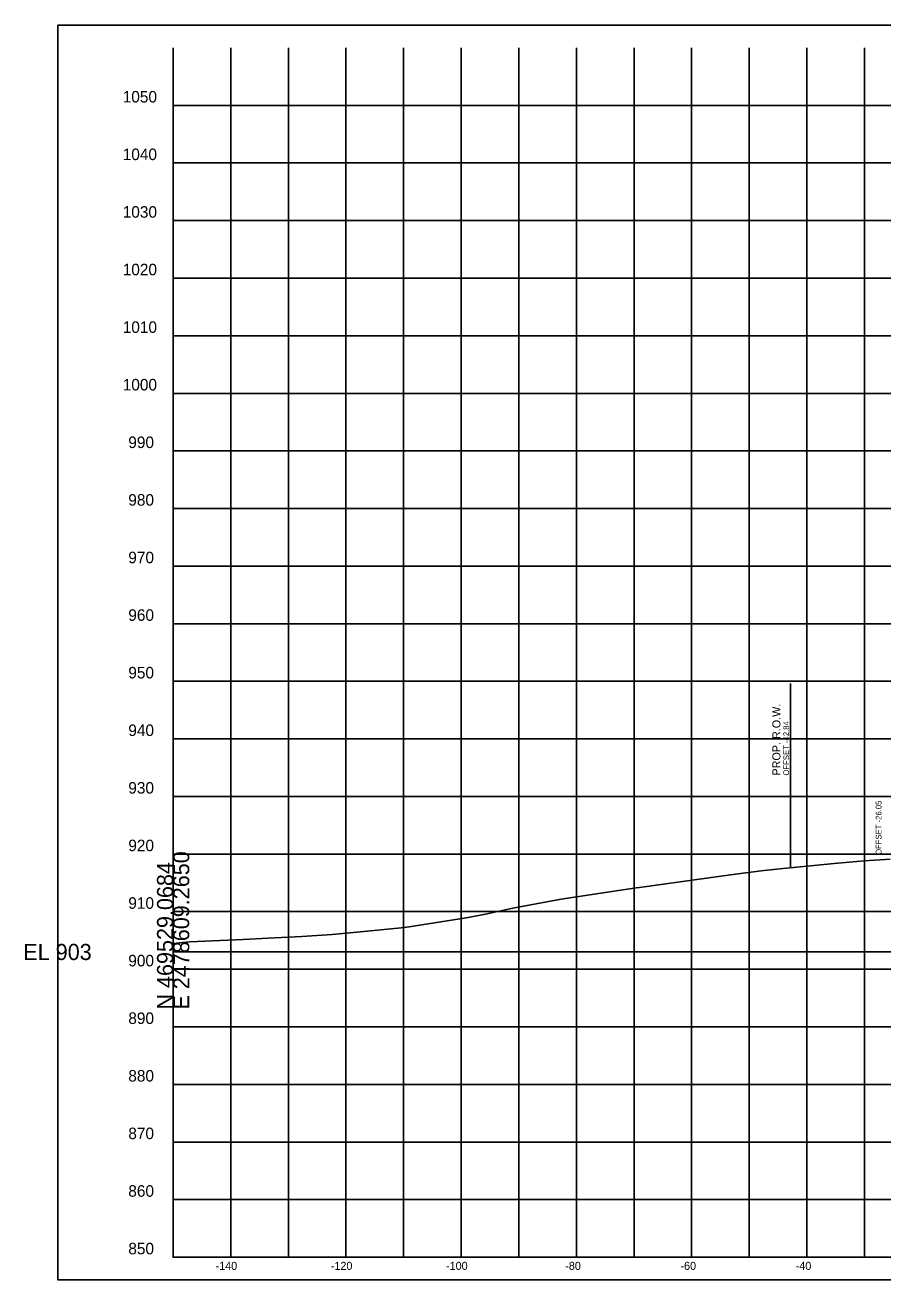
# Model space of a CAD drawing. Extents: x -26 to 2478923, y -10 to 469990.
# Drawn here: x -25.7 to 123.2, y 6943.1 to 7160.9 of the extents above; entities that cross this region are included whole.
import ezdxf

# ---------------------------------------------------------------- set-up
doc = ezdxf.new("R2010")
doc.units = 0
for name, color, linetype in [('DESIGN - ROW - Right-of-Way and Easement Labels', 7, 'Continuous'), ('DESIGN - ROW - Right-of-Way Linework', 7, 'Continuous'), ('DESIGN - SHEET - Corner Text', 7, 'Continuous'), ('DESIGN - SHEET - Light Grid', 7, 'Continuous'), ('DESIGN - SHEET - Linework', 7, 'Continuous'), ('DESIGN - SHEET - Plot Shape', 7, 'Continuous'), ('DESIGN - TYPICAL - Slope Tie Text', 7, 'Continuous'), ('SURVEY - GROUND - Top of Ground', 7, 'Continuous')]:
    doc.layers.add(name, color=color, linetype=linetype)

msp = doc.modelspace()

# ---------------------------------------------------------------- linework, layer by layer
at = {"layer": 'DESIGN - ROW - Right-of-Way Linework'}
msp.add_line((107.16, 7014.63), (107.16, 7046.63), dxfattribs=at)
at = {"layer": 'DESIGN - SHEET - Light Grid'}
msp.add_line((0, 7000), (150, 7000), dxfattribs=at)
at = {"layer": 'DESIGN - SHEET - Linework'}
for p, q in [((10, 6947), (10, 7157)), ((10, 6947), (10, 7157)), ((10, 6947), (10, 7157)), ((10, 6947), (10, 7157)), ((20, 6947), (20, 7157)), ((20, 6947), (20, 7157)), ((20, 6947), (20, 7157)), ((20, 6947), (20, 7157)), ((30, 6947), (30, 7157)), ((30, 6947), (30, 7157)), ((30, 6947), (30, 7157)), ((30, 6947), (30, 7157)), ((40, 6947), (40, 7157)), ((40, 6947), (40, 7157)), ((40, 6947), (40, 7157)), ((40, 6947), (40, 7157)), ((50, 6947), (50, 7157)), ((50, 6947), (50, 7157)), ((50, 6947), (50, 7157)), ((50, 6947), (50, 7157)), ((60, 6947), (60, 7157)), ((60, 6947), (60, 7157)), ((60, 6947), (60, 7157)), ((60, 6947), (60, 7157)), ((70, 6947), (70, 7157)), ((70, 6947), (70, 7157)), ((70, 6947), (70, 7157)), ((70, 6947), (70, 7157)), ((80, 6947), (80, 7157)), ((80, 6947), (80, 7157)), ((80, 6947), (80, 7157)), ((80, 6947), (80, 7157)), ((90, 6947), (90, 7157)), ((90, 6947), (90, 7157)), ((90, 6947), (90, 7157)), ((90, 6947), (90, 7157)), ((100, 6947), (100, 7157)), ((100, 6947), (100, 7157)), ((100, 6947), (100, 7157)), ((100, 6947), (100, 7157)), ((110, 6947), (110, 7157)), ((110, 6947), (110, 7157)), ((110, 6947), (110, 7157)), ((110, 6947), (110, 7157)), ((120, 6947), (120, 7157)), ((120, 6947), (120, 7157)), ((120, 6947), (120, 7157)), ((120, 6947), (120, 7157)), ((0, 7147), (300, 7147)), ((0, 7147), (300, 7147)), ((0, 7147), (300, 7147)), ((0, 7147), (300, 7147)), ((0, 7137), (300, 7137)), ((0, 7137), (300, 7137)), ((0, 7137), (300, 7137)), ((0, 7137), (300, 7137)), ((0, 7127), (300, 7127)), ((0, 7127), (300, 7127)), ((0, 7127), (300, 7127)), ((0, 7127), (300, 7127)), ((0, 7117), (300, 7117)), ((0, 7117), (300, 7117)), ((0, 7117), (300, 7117)), ((0, 7117), (300, 7117)), ((0, 7107), (300, 7107)), ((0, 7107), (300, 7107)), ((0, 7107), (300, 7107)), ((0, 7107), (300, 7107)), ((0, 7097), (300, 7097)), ((0, 7097), (300, 7097)), ((0, 7097), (300, 7097)), ((0, 7097), (300, 7097)), ((0, 7087), (300, 7087)), ((0, 7087), (300, 7087)), ((0, 7087), (300, 7087)), ((0, 7087), (300, 7087)), ((0, 7077), (300, 7077)), ((0, 7077), (300, 7077)), ((0, 7077), (300, 7077)), ((0, 7077), (300, 7077)), ((0, 7067), (300, 7067)), ((0, 7067), (300, 7067)), ((0, 7067), (300, 7067)), ((0, 7067), (300, 7067)), ((0, 7057), (300, 7057)), ((0, 7057), (300, 7057)), ((0, 7057), (300, 7057)), ((0, 7057), (300, 7057)), ((0, 7047), (300, 7047)), ((0, 7047), (300, 7047)), ((0, 7047), (300, 7047)), ((0, 7047), (300, 7047)), ((0, 7037), (300, 7037)), ((0, 7037), (300, 7037)), ((0, 7037), (300, 7037)), ((0, 7037), (300, 7037)), ((0, 7027), (300, 7027)), ((0, 7027), (300, 7027)), ((0, 7027), (300, 7027)), ((0, 7027), (300, 7027)), ((0, 7017), (300, 7017)), ((0, 7017), (300, 7017)), ((0, 7017), (300, 7017)), ((0, 7017), (300, 7017)), ((0, 7007), (300, 7007)), ((0, 7007), (300, 7007)), ((0, 7007), (300, 7007)), ((0, 7007), (300, 7007)), ((0, 6997), (300, 6997)), ((0, 6997), (300, 6997)), ((0, 6997), (300, 6997)), ((0, 6997), (300, 6997)), ((0, 6987), (300, 6987)), ((0, 6987), (300, 6987)), ((0, 6987), (300, 6987)), ((0, 6987), (300, 6987)), ((0, 6977), (300, 6977)), ((0, 6977), (300, 6977)), ((0, 6977), (300, 6977)), ((0, 6977), (300, 6977)), ((0, 6967), (300, 6967)), ((0, 6967), (300, 6967)), ((0, 6967), (300, 6967)), ((0, 6967), (300, 6967)), ((0, 6957), (300, 6957)), ((0, 6957), (300, 6957)), ((0, 6957), (300, 6957)), ((0, 6957), (300, 6957))]:
    msp.add_line(p, q, dxfattribs=at)
msp.add_lwpolyline([(0, 7157), (0, 6947), (300, 6947), (300, 7157)], dxfattribs=at)
msp.add_lwpolyline([(0, 7157), (0, 6947), (300, 6947), (300, 7157)], dxfattribs=at)
msp.add_lwpolyline([(0, 7157), (0, 6947), (300, 6947), (300, 7157)], dxfattribs=at)
msp.add_lwpolyline([(0, 7157), (0, 6947), (300, 6947), (300, 7157)], dxfattribs=at)
at = {"layer": 'DESIGN - SHEET - Plot Shape'}
msp.add_lwpolyline([(-20, 7160.94), (320, 7160.94), (320, 6943.06), (-20, 6943.06)], close=True, dxfattribs=at)
msp.add_lwpolyline([(-20, 7160.94), (320, 7160.94), (320, 6943.06), (-20, 6943.06)], close=True, dxfattribs=at)
msp.add_lwpolyline([(-20, 7160.94), (320, 7160.94), (320, 6943.06), (-20, 6943.06)], close=True, dxfattribs=at)
msp.add_lwpolyline([(-20, 7160.94), (320, 7160.94), (320, 6943.06), (-20, 6943.06)], close=True, dxfattribs=at)
at = {"layer": 'SURVEY - GROUND - Top of Ground'}
msp.add_lwpolyline([(0, 7001.49), (2.84, 7001.75), (12.16, 7002.18), (16.51, 7002.4), (22.32, 7002.66), (27.62, 7003.04), (33.08, 7003.58), (40.14, 7004.26), (40.48, 7004.29), (40.96, 7004.36), (50.85, 7005.92), (54.22, 7006.57), (58.97, 7007.63), (67.37, 7009.19), (80.36, 7011.14), (80.93, 7011.22), (92.57, 7012.8), (96.75, 7013.4), (102.07, 7014.08), (105.89, 7014.51), (114.71, 7015.38), (117.35, 7015.6), (119.98, 7015.82), (124.47, 7016.14)], dxfattribs=at)

# ---------------------------------------------------------------- texts
at = {"layer": 'DESIGN - ROW - Right-of-Way and Easement Labels'}
for s, height, p in [('PROP. R.O.W.', 1.4, (105.41, 7030.63)), ('OFFSET -42.84', 1, (106.91, 7030.63))]:
    msp.add_text(s, height=height, rotation=90, dxfattribs=at).set_placement(p)
at = {"layer": 'DESIGN - SHEET - Corner Text'}
for s, height, p in [('1050', 2, (-8.75, 7147.5)), ('1050', 2, (-8.75, 7147.5)), ('1050', 2, (-8.75, 7147.5)), ('1050', 2, (-8.75, 7147.5)), ('1040', 2, (-8.75, 7137.5)), ('1040', 2, (-8.75, 7137.5)), ('1040', 2, (-8.75, 7137.5)), ('1040', 2, (-8.75, 7137.5)), ('1030', 2, (-8.75, 7127.5)), ('1030', 2, (-8.75, 7127.5)), ('1030', 2, (-8.75, 7127.5)), ('1030', 2, (-8.75, 7127.5)), ('1020', 2, (-8.75, 7117.5)), ('1020', 2, (-8.75, 7117.5)), ('1020', 2, (-8.75, 7117.5)), ('1020', 2, (-8.75, 7117.5)), ('1010', 2, (-8.75, 7107.5)), ('1010', 2, (-8.75, 7107.5)), ('1010', 2, (-8.75, 7107.5)), ('1010', 2, (-8.75, 7107.5)), ('1000', 2, (-8.75, 7097.5)), ('1000', 2, (-8.75, 7097.5)), ('1000', 2, (-8.75, 7097.5)), ('1000', 2, (-8.75, 7097.5)), ('990', 2, (-7.78, 7087.5)), ('990', 2, (-7.78, 7087.5)), ('990', 2, (-7.78, 7087.5)), ('990', 2, (-7.78, 7087.5)), ('980', 2, (-7.78, 7077.5)), ('980', 2, (-7.78, 7077.5)), ('980', 2, (-7.78, 7077.5)), ('980', 2, (-7.78, 7077.5)), ('970', 2, (-7.78, 7067.5)), ('970', 2, (-7.78, 7067.5)), ('970', 2, (-7.78, 7067.5)), ('970', 2, (-7.78, 7067.5)), ('960', 2, (-7.78, 7057.5)), ('960', 2, (-7.78, 7057.5)), ('960', 2, (-7.78, 7057.5)), ('960', 2, (-7.78, 7057.5)), ('950', 2, (-7.78, 7047.5)), ('950', 2, (-7.78, 7047.5)), ('950', 2, (-7.78, 7047.5)), ('950', 2, (-7.78, 7047.5)), ('940', 2, (-7.78, 7037.5)), ('940', 2, (-7.78, 7037.5)), ('940', 2, (-7.78, 7037.5)), ('940', 2, (-7.78, 7037.5)), ('930', 2, (-7.78, 7027.5)), ('930', 2, (-7.78, 7027.5)), ('930', 2, (-7.78, 7027.5)), ('930', 2, (-7.78, 7027.5)), ('920', 2, (-7.78, 7017.5)), ('920', 2, (-7.78, 7017.5)), ('920', 2, (-7.78, 7017.5)), ('920', 2, (-7.78, 7017.5)), ('910', 2, (-7.78, 7007.5)), ('910', 2, (-7.78, 7007.5)), ('910', 2, (-7.78, 7007.5)), ('910', 2, (-7.78, 7007.5)), ('900', 2, (-7.78, 6997.5)), ('900', 2, (-7.78, 6997.5)), ('900', 2, (-7.78, 6997.5)), ('900', 2, (-7.78, 6997.5)), ('890', 2, (-7.78, 6987.5)), ('890', 2, (-7.78, 6987.5)), ('890', 2, (-7.78, 6987.5)), ('890', 2, (-7.78, 6987.5)), ('880', 2, (-7.78, 6977.5)), ('880', 2, (-7.78, 6977.5)), ('880', 2, (-7.78, 6977.5)), ('880', 2, (-7.78, 6977.5)), ('870', 2, (-7.78, 6967.5)), ('870', 2, (-7.78, 6967.5)), ('870', 2, (-7.78, 6967.5)), ('870', 2, (-7.78, 6967.5)), ('860', 2, (-7.78, 6957.5)), ('860', 2, (-7.78, 6957.5)), ('860', 2, (-7.78, 6957.5)), ('860', 2, (-7.78, 6957.5)), ('850', 2, (-7.78, 6947.5)), ('850', 2, (-7.78, 6947.5)), ('850', 2, (-7.78, 6947.5)), ('850', 2, (-7.78, 6947.5)), ('-140', 1.4, (7.37, 6944.8)), ('-140', 1.4, (7.37, 6944.8)), ('-140', 1.4, (7.37, 6944.8)), ('-140', 1.4, (7.37, 6944.8)), ('-120', 1.4, (27.37, 6944.8)), ('-120', 1.4, (27.37, 6944.8)), ('-120', 1.4, (27.37, 6944.8)), ('-120', 1.4, (27.37, 6944.8)), ('-100', 1.4, (47.37, 6944.8)), ('-100', 1.4, (47.37, 6944.8)), ('-100', 1.4, (47.37, 6944.8)), ('-100', 1.4, (47.37, 6944.8)), ('-80', 1.4, (68.06, 6944.8)), ('-80', 1.4, (68.06, 6944.8)), ('-80', 1.4, (68.06, 6944.8)), ('-80', 1.4, (68.06, 6944.8)), ('-60', 1.4, (88.06, 6944.8)), ('-60', 1.4, (88.06, 6944.8)), ('-60', 1.4, (88.06, 6944.8)), ('-60', 1.4, (88.06, 6944.8)), ('-40', 1.4, (108.06, 6944.8)), ('-40', 1.4, (108.06, 6944.8)), ('-40', 1.4, (108.06, 6944.8)), ('-40', 1.4, (108.06, 6944.8))]:
    msp.add_text(s, height=height, dxfattribs=at).set_placement(p)
at = {"layer": 'DESIGN - SHEET - Light Grid'}
for s, p in [('E 2478609.2650', (2.8, 6990)), ('N 469529.0684', (0, 6990))]:
    msp.add_text(s, height=2.8, rotation=90, dxfattribs=at).set_placement(p)
msp.add_text('EL 903', height=2.8, dxfattribs=at).set_placement((-26, 6998.6))
at = {"layer": 'DESIGN - TYPICAL - Slope Tie Text'}
msp.add_text('OFFSET -26.05', height=1, rotation=90, dxfattribs=at).set_placement((122.95, 7016.85))

doc.saveas('drawing.dxf')
